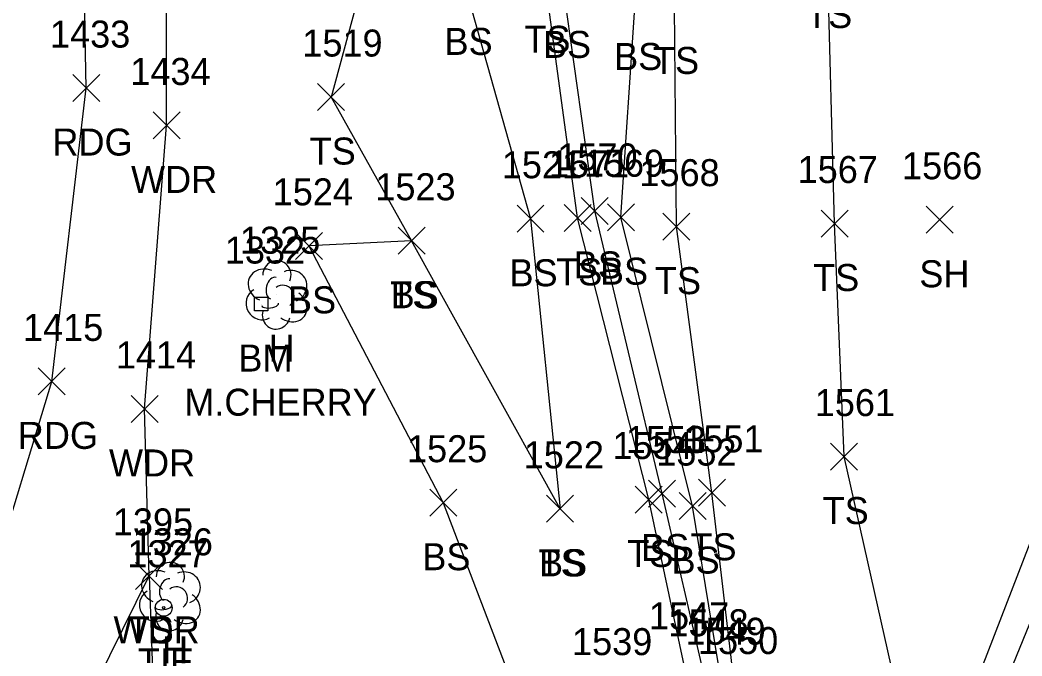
# Model space of a CAD drawing. Extents: x 1600281 to 1602254, y 862855 to 863227.
# Drawn here: x 1602032.3 to 1602106.5, y 862931.1 to 862978.2 of the extents above; entities that cross this region are included whole.
import ezdxf

# ---------------------------------------------------------------- set-up
doc = ezdxf.new("R2010")
doc.units = 0
for name, color, linetype in [('C_A', 7, 'Continuous'), ('C_I', 7, 'Continuous'), ('CBP', 7, 'Continuous'), ('CPBM', 7, 'Continuous'), ('L_A', 7, 'Continuous'), ('L_C', 7, 'Continuous'), ('L_I', 7, 'Continuous'), ('L_TIC', 7, 'Continuous'), ('LAWA', 7, 'Continuous'), ('LAWE', 7, 'Continuous'), ('LELB', 7, 'Continuous'), ('LTD', 7, 'Continuous'), ('P_A', 7, 'Continuous'), ('P_I', 7, 'Continuous'), ('P_TIC', 7, 'Continuous'), ('PEU', 7, 'Continuous')]:
    doc.layers.add(name, color=color, linetype=linetype)

msp = doc.modelspace()

# ---------------------------------------------------------------- linework, layer by layer
at = {"layer": 'CBP'}
for radius in [0.625, 0.0833]:
    msp.add_circle((1602042.905, 862934.64), radius, dxfattribs=at)
at = {"layer": 'CPBM'}
for p, q in [((1602049.62, 862956.637), (1602049.62, 862957.637)), ((1602049.62, 862957.637), (1602050.62, 862957.637)), ((1602050.122, 862957.138), (1602050.122, 862957.138)), ((1602050.122, 862957.138), (1602050.122, 862957.138)), ((1602050.62, 862957.637), (1602050.62, 862956.637)), ((1602050.62, 862956.637), (1602049.62, 862956.637))]:
    msp.add_line(p, q, dxfattribs=at)
at = {"layer": 'L_TIC'}
for points in [[(1602054.31, 862971.472), (1602056.31, 862973.472)], [(1602056.31, 862971.472), (1602054.31, 862973.472)], [(1602042.119, 862969.368), (1602044.119, 862971.368)], [(1602044.119, 862969.368), (1602042.119, 862971.368)], [(1602072.583, 862962.521), (1602074.583, 862964.521)], [(1602074.583, 862962.521), (1602072.583, 862964.521)], [(1602073.854, 862963.036), (1602075.854, 862965.036)], [(1602075.854, 862963.036), (1602073.854, 862965.036)], [(1602075.793, 862962.57), (1602077.793, 862964.57)], [(1602077.793, 862962.57), (1602075.793, 862964.57)], [(1602069.089, 862962.456), (1602071.089, 862964.456)], [(1602071.089, 862962.456), (1602069.089, 862964.456)], [(1602079.901, 862961.87), (1602081.901, 862963.87)], [(1602081.901, 862961.87), (1602079.901, 862963.87)], [(1602091.628, 862962.103), (1602093.628, 862964.103)], [(1602093.628, 862962.103), (1602091.628, 862964.103)], [(1602099.42, 862962.381), (1602101.42, 862964.381)], [(1602101.42, 862962.381), (1602099.42, 862964.381)], [(1602052.671, 862960.449), (1602054.671, 862962.449)], [(1602054.671, 862960.449), (1602052.671, 862962.449)], [(1602060.28, 862960.826), (1602062.28, 862962.826)], [(1602062.28, 862960.826), (1602060.28, 862962.826)], [(1602060.28, 862960.826), (1602062.28, 862962.826)], [(1602062.28, 862960.826), (1602060.28, 862962.826)], [(1602060.28, 862960.826), (1602062.28, 862962.826)], [(1602062.28, 862960.826), (1602060.28, 862962.826)], [(1602040.484, 862948.365), (1602042.484, 862950.365)], [(1602042.484, 862948.365), (1602040.484, 862950.365)], [(1602092.331, 862944.837), (1602094.331, 862946.837)], [(1602094.331, 862944.837), (1602092.331, 862946.837)], [(1602078.846, 862942.099), (1602080.846, 862944.099)], [(1602080.846, 862942.099), (1602078.846, 862944.099)], [(1602082.535, 862942.154), (1602084.535, 862944.154)], [(1602084.535, 862942.154), (1602082.535, 862944.154)], [(1602062.628, 862941.421), (1602064.628, 862943.421)], [(1602064.628, 862941.421), (1602062.628, 862943.421)], [(1602071.28, 862940.969), (1602073.28, 862942.969)], [(1602073.28, 862940.969), (1602071.28, 862942.969)], [(1602071.28, 862940.969), (1602073.28, 862942.969)], [(1602073.28, 862940.969), (1602071.28, 862942.969)], [(1602077.855, 862941.657), (1602079.855, 862943.657)], [(1602079.855, 862941.657), (1602077.855, 862943.657)], [(1602081.101, 862941.173), (1602083.101, 862943.173)], [(1602083.101, 862941.173), (1602081.101, 862943.173)], [(1602040.823, 862935.999), (1602042.823, 862937.999)], [(1602042.823, 862935.999), (1602040.823, 862937.999)], [(1602040.823, 862935.999), (1602042.823, 862937.999)], [(1602042.823, 862935.999), (1602040.823, 862937.999)]]:
    msp.add_lwpolyline(points, dxfattribs=at)
at = {"layer": 'LAWA'}
for points in [[(1602013.88, 862864.604), (1602012.852, 862879.286), (1602012.389, 862885.249), (1602013.668, 862890.426), (1602013.993, 862891.89), (1602014.423, 862895.34), (1602031.133, 862915.343), (1602041.823, 862936.999), (1602041.484, 862949.365), (1602043.119, 862970.368), (1602043.104, 862998.4), (1602042.776, 863006.718), (1602043.565, 863021.702), (1602048.724, 863030.448), (1602052.915, 863023.582), (1602057.074, 863015.497), (1602062.849, 863014.974)], [(1602096.406, 862879.641), (1602095.369, 862902.033), (1602099.326, 862919.262), (1602109.634, 862945.957), (1602110.967, 862962.959), (1602110.328, 862983.187), (1602104.696, 862999.605), (1602098.833, 863009.484), (1602089.047, 863018.841), (1602087.063, 863019.481), (1602084.93, 863020.571), (1602083.846, 863020.871), (1602075.62, 863029.355), (1602062.849, 863014.974)]]:
    msp.add_lwpolyline(points, dxfattribs=at)
at = {"layer": 'LAWE'}
msp.add_lwpolyline([(1602098.435, 862879.183), (1602097.38, 862900.93), (1602100.821, 862918.119), (1602111.897, 862945.191), (1602113.655, 862964.279), (1602114.598, 862983.415), (1602109.052, 863000.365), (1602100.599, 863011.379), (1602088.422, 863022.641), (1602086.169, 863023.524), (1602076.977, 863030.193), (1602067.142, 863034.999), (1602054.868, 863040.585)], dxfattribs=at)
at = {"layer": 'LELB'}
for points in [[(1601758.874, 862935.581), (1601794.57, 862931.041), (1601823.257, 862926.647), (1601871.558, 862921.026), (1601900.015, 862918.494), (1601930.467, 862913.509), (1601956.156, 862906.35), (1601972.874, 862902.678), (1601993.622, 862897.851), (1602007.259, 862890.971), (1602013.993, 862891.89), (1602036.738, 862896.625), (1602039.12, 862902.94), (1602042.648, 862913.223), (1602071.455, 862922.172), (1602077.729, 862924.942), (1602082.998, 862929.527), (1602079.846, 862943.099), (1602074.854, 862964.036), (1602072.569, 862980.371), (1602075.414, 862992.31), (1602081.733, 863011.092), (1602084.93, 863020.571), (1602086.169, 863023.524)], [(1601758.252, 862932.382), (1601793.251, 862926.874), (1601822.781, 862921.72), (1601870.875, 862915.198), (1601899.959, 862912.838), (1601929.995, 862911.268), (1601955.114, 862904.27), (1601972.397, 862900.453), (1601993.867, 862895.104), (1602006.953, 862889.055), (1602013.668, 862890.426), (1602037.377, 862895.193), (1602041.453, 862902.138), (1602044.339, 862911.825), (1602073.391, 862917.1), (1602080.565, 862918.061), (1602084.273, 862928.901), (1602082.101, 862942.173), (1602076.793, 862963.57), (1602077.845, 862979.478), (1602084.814, 862995.174), (1602084.825, 863009.345), (1602087.063, 863019.481), (1602088.422, 863022.641)], [(1602043.565, 863021.702), (1602050.721, 863012.929), (1602058.497, 862993.658), (1602059.334, 862987.347), (1602055.31, 862972.472), (1602061.28, 862961.826)], [(1601758.889, 862937.881), (1601795.072, 862933.903), (1601823.846, 862928.868), (1601870.343, 862922.924), (1601900.351, 862921.152), (1601930.516, 862914.56), (1601956.196, 862907.256), (1601973.319, 862904.611), (1601993.849, 862899.996), (1602008.191, 862895.024), (1602014.423, 862895.34), (1602035.615, 862898.845), (1602036.447, 862903.94), (1602042.391, 862916.03), (1602070.541, 862924.323), (1602075.868, 862928.131), (1602081.563, 862930.038), (1602078.855, 862942.657), (1602073.583, 862963.521), (1602071.226, 862980.749), (1602072.263, 862993.358), (1602076.694, 863007.703), (1602078.086, 863013.394), (1602083.846, 863020.871)], [(1601994.69, 862890.807), (1602005.018, 862886.613), (1602012.389, 862885.249), (1602036.932, 862893.166), (1602042.387, 862901.65), (1602044.794, 862907.826), (1602074.596, 862913.524), (1602080.814, 862915.532), (1602085.28, 862928.211), (1602083.535, 862943.154), (1602080.901, 862962.87), (1602080.76, 862979.184), (1602088.297, 862994.751), (1602086.854, 863009.161), (1602089.047, 863018.841)], [(1602057.074, 863015.497), (1602065.481, 863007.744), (1602068.287, 862994.511), (1602065.274, 862980.593), (1602070.089, 862963.456), (1602072.28, 862941.969)], [(1602099.326, 862919.262), (1602093.331, 862945.837), (1602092.628, 862963.103), (1602092.109, 862982.585), (1602088.297, 862994.751)], [(1602061.28, 862961.826), (1602053.671, 862961.449), (1602063.628, 862942.421), (1602070.541, 862924.323), (1602071.455, 862922.172), (1602073.391, 862917.1), (1602074.596, 862913.524), (1602067.958, 862895.711), (1602074.24, 862873.53)], [(1602072.28, 862941.969), (1602061.28, 862961.826)], [(1602041.823, 862936.999), (1602042.344, 862922.347), (1602042.391, 862916.03)]]:
    msp.add_lwpolyline(points, dxfattribs=at)
at = {"layer": 'LTD'}
for p, q in [((1602051.247, 862957.866), (1602051.247, 862957.866)), ((1602051.247, 862957.866), (1602051.247, 862957.866)), ((1602043.347, 862935.524), (1602043.347, 862935.524)), ((1602043.347, 862935.524), (1602043.347, 862935.524))]:
    msp.add_line(p, q, dxfattribs=at)
for centre in [(1602051.294, 862959.3), (1602043.394, 862936.958)]:
    msp.add_arc(centre, 1.047, 335.52715, 180.95627, dxfattribs=at)
for centre, major_axis, ratio, start_param, end_param in [((1602050.455, 862958.532), (1.21, -0.512), 0.895232, 1.570796, 4.712389), ((1602052.288, 862958.449), (-1.141, -0.483), 0.949671, 1.570796, 4.712389), ((1602051.038, 862958.324), (-0.208, -0.792), 0.645439, 3.141593, 6.283185), ((1602051.747, 862957.699), (-0.5, 0.667), 0.989748, 3.141593, 6.283185), ((1602050.164, 862957.157), (0.584, -1.042), 0.959034, 3.141593, 6.283185), ((1602052.247, 862957.033), (-1.09, 0.792), 0.841452, 1.570796, 4.712389), ((1602050.789, 862957.116), (-0.625, -0.083), 0.423636, 0, 3.141593), ((1602051.247, 862956.366), (0.265, 1.061), 0.942809, 1.570796, 4.712389), ((1602042.555, 862936.19), (1.21, -0.512), 0.895232, 1.570796, 4.712389), ((1602044.388, 862936.107), (-1.141, -0.483), 0.949671, 1.570796, 4.712389), ((1602043.138, 862935.982), (-0.208, -0.792), 0.645439, 3.141593, 6.283185), ((1602043.847, 862935.357), (-0.5, 0.667), 0.989748, 3.141593, 6.283185), ((1602042.264, 862934.815), (0.584, -1.042), 0.959034, 3.141593, 6.283185), ((1602044.347, 862934.691), (-1.09, 0.792), 0.841452, 1.570796, 4.712389), ((1602042.889, 862934.774), (-0.625, -0.083), 0.423636, 0, 3.141593), ((1602043.347, 862934.024), (0.265, 1.061), 0.942809, 1.570796, 4.712389)]:
    msp.add_ellipse(centre, major_axis=major_axis, ratio=ratio, start_param=start_param, end_param=end_param, dxfattribs=at)
at = {"layer": 'P_TIC'}
for points in [[(1602036.167, 862972.137), (1602038.167, 862974.137)], [(1602038.167, 862972.137), (1602036.167, 862974.137)], [(1602033.602, 862950.409), (1602035.602, 862952.409)], [(1602035.602, 862950.409), (1602033.602, 862952.409)]]:
    msp.add_lwpolyline(points, dxfattribs=at)
at = {"layer": 'PEU'}
msp.add_lwpolyline([(1601721.431, 862942.479), (1601759.391, 862940.415), (1601795.476, 862935.046), (1601824.436, 862931.284), (1601871.597, 862925.252), (1601900.947, 862923.392), (1601930.539, 862915.155), (1601956.45, 862910.483), (1601973.532, 862907.721), (1601992.866, 862904.836), (1602011.433, 862910.06), (1602025.54, 862921.56), (1602034.602, 862951.409), (1602037.167, 862973.137), (1602036.63, 863000.366), (1602039.384, 863008.705), (1602041.945, 863026.807), (1602046.402, 863038.482), (1602048.205, 863041.762), (1602041.548, 863045.817), (1602034.191, 863049.728), (1602032.199, 863046.614)], dxfattribs=at)

# ---------------------------------------------------------------- texts
at = {"layer": 'C_A'}
for s, p in [('BM', (1602048.437, 862952.138)), ('TIE', (1602040.983, 862929.64))]:
    msp.add_text(s, height=2, dxfattribs=at).set_placement(p)
at = {"layer": 'C_I'}
for s, p in [('1332', (1602047.429, 862960.138)), ('1327', (1602040.212, 862937.64))]:
    msp.add_text(s, height=2, dxfattribs=at).set_placement(p)
at = {"layer": 'L_A'}
for s, p in [('TS', (1602090.518, 862977.585)), ('BS', (1602063.715, 862975.593)), ('TS', (1602069.636, 862975.749)), ('BS', (1602071.01, 862975.371)), ('BS', (1602076.286, 862974.478)), ('TS', (1602079.169, 862974.184)), ('TS', (1602053.72, 862967.472)), ('WDR', (1602040.481, 862965.368)), ('BS', (1602073.295, 862959.036)), ('BS', (1602068.53, 862958.456)), ('TS', (1602071.992, 862958.521)), ('BS', (1602075.234, 862958.57)), ('TS', (1602091.038, 862958.103)), ('SH', (1602098.908, 862958.381)), ('TS', (1602079.311, 862957.87)), ('TS', (1602059.69, 862956.826)), ('TS', (1602059.69, 862956.826)), ('BS', (1602059.721, 862956.826)), ('BS', (1602052.112, 862956.449)), ('H', (1602050.68, 862952.866)), ('WDR', (1602038.847, 862944.365)), ('TS', (1602091.741, 862940.837)), ('BS', (1602078.287, 862938.099)), ('TS', (1602081.945, 862938.154)), ('BS', (1602062.069, 862937.421)), ('TS', (1602077.264, 862937.657)), ('TS', (1602070.69, 862936.969)), ('BS', (1602070.721, 862936.969)), ('BS', (1602080.542, 862937.173)), ('WDR', (1602039.185, 862931.999)), ('TS', (1602040.233, 862931.999)), ('H', (1602042.78, 862930.524))]:
    msp.add_text(s, height=2, dxfattribs=at).set_placement(p)
at = {"layer": 'L_C'}
msp.add_text('M.CHERRY', height=2, dxfattribs=at).set_placement((1602044.428, 862948.866))
at = {"layer": 'L_I'}
for s, p in [('1519', (1602053.176, 862975.472)), ('1434', (1602040.426, 862973.368)), ('1570', (1602072.075, 862967.036)), ('1521', (1602067.963, 862966.456)), ('1571', (1602071.457, 862966.521)), ('1569', (1602074.045, 862966.57)), ('1566', (1602097.625, 862966.381)), ('1568', (1602078.161, 862965.87)), ('1567', (1602089.888, 862966.103)), ('1523', (1602058.587, 862964.826)), ('1523', (1602058.587, 862964.826)), ('1523', (1602058.587, 862964.826)), ('1524', (1602050.979, 862964.449)), ('1325', (1602048.554, 862960.866)), ('1414', (1602039.358, 862952.365)), ('1561', (1602091.158, 862948.837)), ('1525', (1602060.935, 862945.421)), ('1554', (1602076.162, 862945.657)), ('1553', (1602077.153, 862946.099)), ('1551', (1602081.409, 862946.154)), ('1522', (1602069.587, 862944.969)), ('1522', (1602069.587, 862944.969)), ('1552', (1602079.408, 862945.173)), ('1395', (1602039.13, 862939.999)), ('1395', (1602039.13, 862939.999)), ('1326', (1602040.599, 862938.524)), ('1547', (1602078.87, 862933.038)), ('1548', (1602080.305, 862932.527)), ('1549', (1602081.572, 862931.901)), ('1539', (1602073.167, 862931.131)), ('1550', (1602082.5, 862931.211))]:
    msp.add_text(s, height=2, dxfattribs=at).set_placement(p)
at = {"layer": 'P_A'}
for p in [(1602034.655, 862968.137), (1602032.09, 862946.409)]:
    msp.add_text('RDG', height=2, dxfattribs=at).set_placement(p)
at = {"layer": 'P_I'}
for s, p in [('1433', (1602034.474, 862976.137)), ('1415', (1602032.476, 862954.409))]:
    msp.add_text(s, height=2, dxfattribs=at).set_placement(p)

doc.saveas('drawing.dxf')
